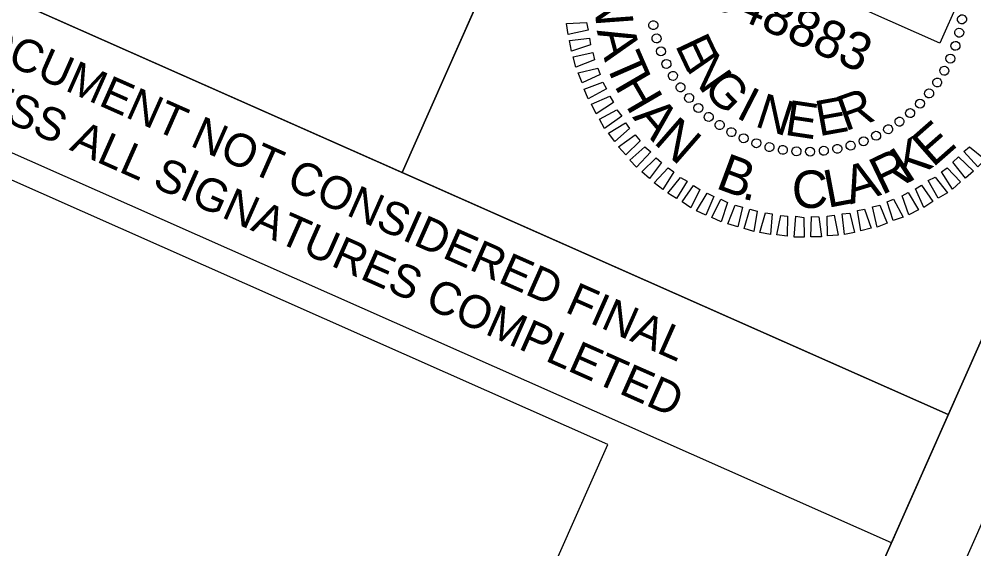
# Model space of a CAD drawing. Extents: x 1637682 to 2864602, y 842496 to 973236.
# Drawn here: x 1639424.2 to 1639584, y 843323.7 to 843412.4 of the extents above; entities that cross this region are included whole.
import ezdxf

# ---------------------------------------------------------------- set-up
doc = ezdxf.new("R2010")
doc.units = 0
for name, color, linetype in [('Default', 7, 'Continuous'), ('Old_Level_2', 7, 'Continuous'), ('Sheet Clip Boundary CELL', 7, 'Continuous'), ('Sheet Plan CELL', 7, 'Continuous'), ('Sheet Plot Border Inside CELL', 7, 'Continuous'), ('Sheet Sticker Exception Certification CELL', 7, 'Continuous'), ('Sheet Sticker Incomplete CELL', 7, 'Continuous')]:
    doc.layers.add(name, color=color, linetype=linetype)

msp = doc.modelspace()

# ---------------------------------------------------------------- linework, layer by layer
at = {"layer": 'Old_Level_2'}
for p, q in [((1639582.03, 843412.4), (1639582.03, 843412.4)), ((1639530.34, 843411.37), (1639530.34, 843411.37)), ((1639530.83, 843409.18), (1639530.83, 843409.18)), ((1639581.52, 843410.12), (1639581.52, 843410.12)), ((1639580.94, 843407.92), (1639580.94, 843407.92)), ((1639531.6, 843406.98), (1639531.6, 843406.98)), ((1639532.48, 843404.9), (1639532.48, 843404.9)), ((1639580.09, 843405.78), (1639580.09, 843405.78)), ((1639533.62, 843402.89), (1639533.62, 843402.89)), ((1639579.05, 843403.72), (1639579.05, 843403.72)), ((1639577.84, 843401.8), (1639577.84, 843401.8)), ((1639534.85, 843400.95), (1639534.85, 843400.95)), ((1639576.55, 843399.96), (1639576.55, 843399.96)), ((1639536.32, 843399.19), (1639536.32, 843399.19)), ((1639575.02, 843398.22), (1639575.02, 843398.22)), ((1639537.88, 843397.51), (1639537.88, 843397.51)), ((1639573.34, 843396.66), (1639573.34, 843396.66)), ((1639539.62, 843395.98), (1639539.62, 843395.98)), ((1639571.58, 843395.19), (1639571.58, 843395.19)), ((1639541.45, 843394.69), (1639541.45, 843394.69)), ((1639543.38, 843393.48), (1639543.38, 843393.48)), ((1639569.64, 843393.96), (1639569.64, 843393.96)), ((1639545.44, 843392.44), (1639545.44, 843392.44)), ((1639547.58, 843391.59), (1639547.58, 843391.59)), ((1639565.55, 843391.94), (1639565.55, 843391.94)), ((1639567.63, 843392.83), (1639567.63, 843392.83)), ((1639549.77, 843391.01), (1639549.77, 843391.01)), ((1639552.06, 843390.5), (1639552.06, 843390.5)), ((1639554.32, 843390.22), (1639554.32, 843390.22)), ((1639556.58, 843390.18), (1639556.58, 843390.18)), ((1639558.86, 843390.35), (1639558.86, 843390.35)), ((1639561.16, 843390.68), (1639561.16, 843390.68)), ((1639563.35, 843391.17), (1639563.35, 843391.17))]:
    msp.add_line(p, q, dxfattribs=at)
for points in [[(1639519.45, 843410.58), (1639516.12, 843409.83), (1639515.82, 843411.66), (1639519.18, 843411.83)], [(1639519.86, 843408.08), (1639516.65, 843407.05), (1639516.32, 843408.84), (1639519.67, 843409.24)], [(1639520.51, 843405.59), (1639517.38, 843404.36), (1639516.92, 843406.09), (1639520.25, 843406.84)], [(1639521.47, 843403.14), (1639518.44, 843401.75), (1639517.77, 843403.4), (1639521.07, 843404.22)], [(1639522.49, 843400.72), (1639519.46, 843399.05), (1639518.79, 843400.7), (1639521.88, 843401.83)], [(1639523.69, 843398.46), (1639520.79, 843396.56), (1639519.98, 843398.15), (1639523.06, 843399.52)], [(1639525.05, 843396.18), (1639522.19, 843394.1), (1639521.36, 843395.64), (1639524.24, 843397.2)], [(1639526.38, 843394.08), (1639523.92, 843391.89), (1639522.82, 843393.32), (1639525.71, 843395.05)], [(1639528.13, 843392.04), (1639525.72, 843389.71), (1639524.51, 843391.01), (1639527.29, 843393.02)], [(1639529.91, 843390.21), (1639527.52, 843387.64), (1639526.41, 843388.79), (1639528.94, 843391.01)], [(1639583.28, 843391.04), (1639585.9, 843388.91), (1639584.64, 843387.68), (1639582.32, 843390.25)], [(1639531.71, 843388.42), (1639529.72, 843385.74), (1639528.43, 843386.86), (1639530.84, 843389.19)], [(1639581.42, 843389.33), (1639583.94, 843386.96), (1639582.58, 843385.77), (1639580.49, 843388.47)], [(1639533.76, 843386.82), (1639531.95, 843383.89), (1639530.48, 843384.97), (1639532.85, 843387.49)], [(1639579.52, 843387.52), (1639581.76, 843385.15), (1639580.4, 843383.96), (1639578.56, 843386.85)], [(1639535.99, 843385.25), (1639534.25, 843382.35), (1639532.76, 843383.27), (1639534.89, 843385.89)], [(1639577.49, 843385.93), (1639579.58, 843383.35), (1639578.04, 843382.41), (1639576.35, 843385.39)], [(1639538.14, 843383.89), (1639536.62, 843380.84), (1639535.15, 843381.8), (1639537.06, 843384.57)], [(1639575.23, 843384.62), (1639577.14, 843381.88), (1639575.63, 843380.87), (1639574.22, 843383.97)], [(1639540.48, 843382.73), (1639539.16, 843379.6), (1639537.59, 843380.32), (1639539.35, 843383.27)], [(1639542.78, 843381.7), (1639541.69, 843378.47), (1639540.12, 843379.19), (1639541.64, 843382.24)], [(1639570.55, 843382.28), (1639572.17, 843379.27), (1639570.5, 843378.67), (1639569.46, 843381.84)], [(1639573.01, 843383.4), (1639574.72, 843380.46), (1639573.13, 843379.66), (1639571.97, 843382.82)], [(1639545.29, 843380.93), (1639544.51, 843377.62), (1639542.79, 843378.12), (1639544.07, 843381.27)], [(1639547.72, 843380.24), (1639547.19, 843376.83), (1639545.54, 843377.36), (1639546.5, 843380.58)], [(1639565.69, 843380.59), (1639566.79, 843377.4), (1639565.06, 843376.94), (1639564.51, 843380.35)], [(1639568.25, 843381.27), (1639569.47, 843378.25), (1639567.83, 843377.59), (1639567.05, 843380.98)], [(1639550.26, 843379.79), (1639549.98, 843376.33), (1639548.2, 843376.68), (1639549.14, 843379.98)], [(1639552.83, 843379.44), (1639552.72, 843376.08), (1639551.04, 843376.28), (1639551.68, 843379.53)], [(1639555.52, 843379.21), (1639555.59, 843375.89), (1639553.9, 843375.92), (1639554.19, 843379.43)], [(1639558.06, 843379.33), (1639558.47, 843375.98), (1639556.69, 843375.94), (1639556.82, 843379.34)], [(1639560.62, 843379.61), (1639561.31, 843376.26), (1639559.49, 843376.12), (1639559.46, 843379.42)], [(1639563.25, 843379.92), (1639564, 843376.71), (1639562.36, 843376.32), (1639561.95, 843379.79)]]:
    msp.add_lwpolyline(points, close=True, dxfattribs=at)
for centre, major_axis in [((1639582.01, 843412.37), (0.744, -0.117)), ((1639530.36, 843411.39), (-0.739, -0.145)), ((1639581.55, 843410.13), (0.731, -0.181)), ((1639530.89, 843409.17), (-0.723, -0.209)), ((1639531.62, 843407), (-0.703, -0.271)), ((1639580.91, 843407.93), (0.712, -0.244)), ((1639580.07, 843405.8), (0.688, -0.305)), ((1639532.54, 843404.9), (-0.676, -0.331)), ((1639579.05, 843403.76), (0.659, -0.364)), ((1639533.63, 843402.89), (-0.645, -0.389)), ((1639534.9, 843400.99), (-0.608, -0.443)), ((1639577.86, 843401.8), (0.625, -0.42)), ((1639536.33, 843399.2), (-0.568, -0.495)), ((1639576.5, 843399.96), (0.586, -0.473)), ((1639537.9, 843397.54), (-0.522, -0.542)), ((1639574.99, 843398.25), (0.542, -0.522)), ((1639539.62, 843396.03), (-0.473, -0.586)), ((1639573.33, 843396.67), (0.495, -0.568)), ((1639541.46, 843394.67), (-0.42, -0.625)), ((1639569.64, 843393.97), (0.389, -0.645)), ((1639571.54, 843395.24), (0.443, -0.608)), ((1639543.41, 843393.48), (-0.364, -0.659)), ((1639545.46, 843392.46), (-0.305, -0.688)), ((1639567.63, 843392.88), (0.331, -0.676)), ((1639547.59, 843391.62), (-0.244, -0.712)), ((1639549.79, 843390.98), (-0.181, -0.731)), ((1639563.36, 843391.24), (0.209, -0.723)), ((1639565.53, 843391.96), (0.271, -0.703)), ((1639552.03, 843390.52), (-0.117, -0.744)), ((1639554.3, 843390.27), (-0.051, -0.751)), ((1639556.59, 843390.21), (0.014, -0.753)), ((1639558.88, 843390.36), (0.08, -0.749)), ((1639561.14, 843390.7), (0.145, -0.739))]:
    msp.add_ellipse(centre, major_axis=major_axis, ratio=0.999708, dxfattribs=at)
at = {"layer": 'Sheet Clip Boundary CELL'}
msp.add_lwpolyline([(1638095.26, 843695.55), (1638010.34, 843303.19), (1637949.73, 843324.57), (1637886.34, 843167.39), (1638760.91, 842777.56), (1638750.92, 842749.91), (1638861.21, 842700.69), (1639015.67, 842665.82), (1639189.46, 842589.52), (1639522.76, 843341.19), (1639380.4, 843404.31), (1639446.06, 843552.39), (1639089.07, 843710.68), (1638988.3, 843567.43), (1638956.05, 843552.43), (1638629.84, 843695.47), (1638719.07, 843884.38), (1638267, 844086.34)], close=True, dxfattribs=at)
at = {"layer": 'Sheet Plan CELL'}
msp.add_line((1639533.9, 843489.6), (1639488.32, 843386.79), dxfattribs=at)
for points in [[(1639640.56, 843483.39), (1638269.28, 844091.43), (1637843.67, 843131.56), (1639214.92, 842523.53)], [(1637843.67, 843131.56), (1638269.25, 844091.42), (1639457.67, 843564.51), (1639396.85, 843427.32), (1639579.71, 843346.22), (1639214.92, 842523.53)], [(1639442.43, 843530.16), (1639533.9, 843489.6), (1639488.29, 843386.75), (1639396.85, 843427.32)], [(1639533.9, 843489.6), (1639625.31, 843449.08), (1639579.71, 843346.22), (1639488.29, 843386.75)]]:
    msp.add_lwpolyline(points, close=True, dxfattribs=at)
at = {"layer": 'Sheet Plot Border Inside CELL'}
msp.add_lwpolyline([(1637702.34, 843191.48), (1639225.33, 842516.19), (1639652.97, 843480.61), (1638129.98, 844155.92)], close=True, dxfattribs=at)
at = {"layer": 'Sheet Sticker Exception Certification CELL'}
for p, q in [((1639396.85, 843427.32), (1639579.72, 843346.23)), ((1639396.85, 843427.32), (1639579.72, 843346.23)), ((1639570.19, 843324.75), (1639387.32, 843405.84)), ((1639570.19, 843324.75), (1639387.32, 843405.84)), ((1639579.71, 843346.22), (1639570.19, 843324.74)), ((1639579.71, 843346.22), (1639570.19, 843324.74))]:
    msp.add_line(p, q, dxfattribs=at)
at = {"layer": 'Sheet Sticker Incomplete CELL'}
msp.add_lwpolyline([(1639443.9, 843467.97), (1639453.43, 843489.46), (1639587.81, 843429.87), (1639578.29, 843408.39)], close=True, dxfattribs=at)

# ---------------------------------------------------------------- texts
at = {"layer": 'Default'}
for s, rotation, p in [('N', 274.1644, (1639520.36, 843417.08)), ('A', 284.7762, (1639520.85, 843410.49)), ('T', 293.5225, (1639522.15, 843405.19)), ('H', 300.2504, (1639523.7, 843401.29)), ('A', 310.1283, (1639526.76, 843395.96)), ('N', 318.8746, (1639530.21, 843391.73)), ('E', 41.307, (1639577.13, 843387.46)), ('K', 33.1111, (1639572.79, 843384.76)), ('R', 25.7104, (1639568.58, 843382.88)), ('B', 339.5782, (1639540.6, 843384.17)), ('C', 1.2758, (1639553.6, 843380.72)), ('L', 10.756, (1639559.51, 843380.79)), ('A', 16.9641, (1639563.34, 843381.37)), ('.', 347.193, (1639545, 843382.4))]:
    msp.add_text(s, height=6.27, rotation=rotation, dxfattribs=at).set_placement(p)
at = {"layer": 'Old_Level_2'}
for s, height, rotation, p in [('048883', 6.275, 336.0871, (1639539.51, 843414.69)), ('E', 5.9, 295.364, (1639533.92, 843408.04)), ('N', 5.9, 304.7211, (1639535.72, 843404.22)), ('G', 5.9, 314.0774, (1639538.46, 843400.5)), ('I', 5.9, 332.7883, (1639544, 843396)), ('N', 5.9, 342.1435, (1639547.16, 843394.5)), ('R', 5.9, 19.5685, (1639562.45, 843393.6)), ('E', 5.9, 351.4989, (1639552.17, 843393.06)), ('E', 5.9, 10.2112, (1639558.07, 843392.78))]:
    msp.add_text(s, height=height, rotation=rotation, dxfattribs=at).set_placement(p)
at = {"layer": 'Sheet Sticker Exception Certification CELL'}
for s, p in [('DOCUMENT NOT CONSIDERED FINAL', (1639411.92, 843409.32)), ('DOCUMENT NOT CONSIDERED FINAL', (1639411.92, 843409.32)), ('UNLESS ALL SIGNATURES COMPLETED', (1639403.72, 843403.33)), ('UNLESS ALL SIGNATURES COMPLETED', (1639403.72, 843403.33))]:
    msp.add_text(s, height=5.5, rotation=336.0871, dxfattribs=at).set_placement(p)

doc.saveas('drawing.dxf')
